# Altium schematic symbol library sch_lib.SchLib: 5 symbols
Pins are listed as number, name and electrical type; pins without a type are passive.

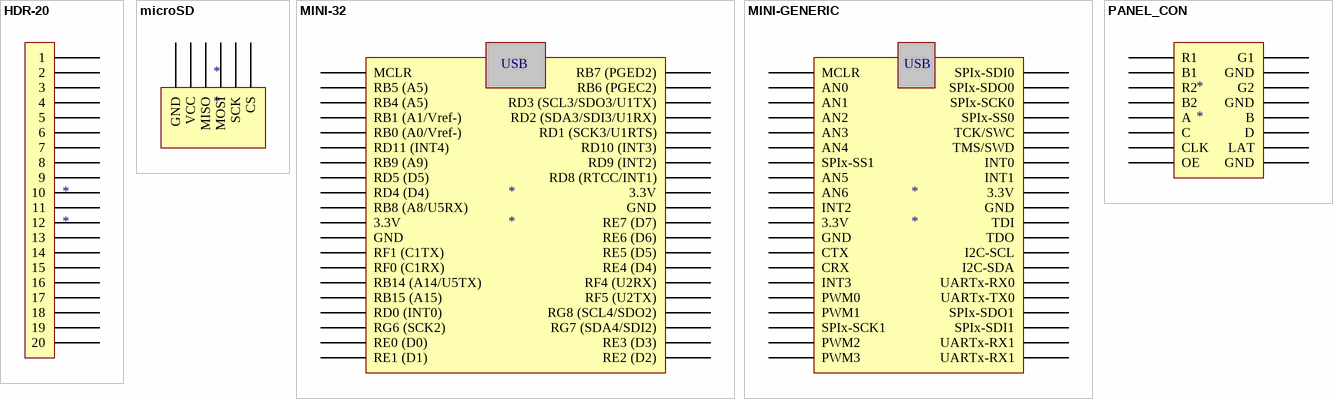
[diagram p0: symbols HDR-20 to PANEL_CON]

## HDR-20
designator *
footprint HDR-20
pins: 1, 2, 3, 4, 5, 6, 7, 8, 9, 10, 11, 12, 13, 14, 15, 16, 17, 18, 19, 20

## microSD
designator *
footprint microSD
pins: 1 GND, 2 VCC, 3 MISO, 4 MOSI, 5 SCK, 6 CS

## MINI-32
designator *
footprint DIP-40
pins: 1 MCLR, 2 RB5 (A5), 3 RB4 (A5), 4 RB1 (A1/Vref-), 5 RB0 (A0/Vref-), 6 RD11 (INT4), 7 RB9 (A9), 8 RD5 (D5), 9 RD4 (D4), 10 RB8 (A8/U5RX), 11 3.3V, 12 GND, 13 RF1 (C1TX), 14 RF0 (C1RX), 15 RB14 (A14/U5TX), 16 RB15 (A15), 17 RD0 (INT0), 18 RG6 (SCK2), 19 RE0 (D0), 20 RE1 (D1), 21 RE2 (D2), 22 RE3 (D3), 23 RG7 (SDA4/SDI2), 24 RG8 (SCL4/SDO2), 25 RF5 (U2TX), 26 RF4 (U2RX), 27 RE4 (D4), 28 RE5 (D5), 29 RE6 (D6), 30 RE7 (D7), 31 GND, 32 3.3V, 33 RD8 (RTCC/INT1), 34 RD9 (INT2), 35 RD10 (INT3), 36 RD1 (SCK3/U1RTS), 37 RD2 (SDA3/SDI3/U1RX), 38 RD3 (SCL3/SDO3/U1TX), 39 RB6 (PGEC2), 40 RB7 (PGED2)

## MINI-GENERIC
designator *
footprint MINI - GENERIC
pins: 1 MCLR, 2 AN0, 3 AN1, 4 AN2, 5 AN3, 6 AN4, 7 SPIx-SS1, 8 AN5, 9 AN6, 10 INT2, 11 3.3V, 12 GND, 13 CTX, 14 CRX, 15 INT3, 16 PWM0, 17 PWM1, 18 SPIx-SCK1, 19 PWM2, 20 PWM3, 21 UARTx-RX1, 22 UARTx-RX1, 23 SPIx-SDI1, 24 SPIx-SDO1, 25 UARTx-TX0, 26 UARTx-RX0, 27 I2C-SDA, 28 I2C-SCL, 29 TDO, 30 TDI, 31 GND, 32 3.3V, 33 INT1, 34 INT0, 35 TMS/SWD, 36 TCK/SWC, 37 SPIx-SS0, 38 SPIx-SCK0, 39 SPIx-SDO0, 40 SPIx-SDI0

## PANEL_CON
designator *
footprint HDR-8x2
pins: 1 R1, 2 B1, 3 R2, 4 B2, 5 A, 6 C, 7 CLK, 8 OE, 9 GND, 10 LAT, 11 D, 12 B, 13 GND, 14 G2, 15 GND, 16 G1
